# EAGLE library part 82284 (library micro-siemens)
MICROPROCESSOR/PERIPHERAL DEVICE
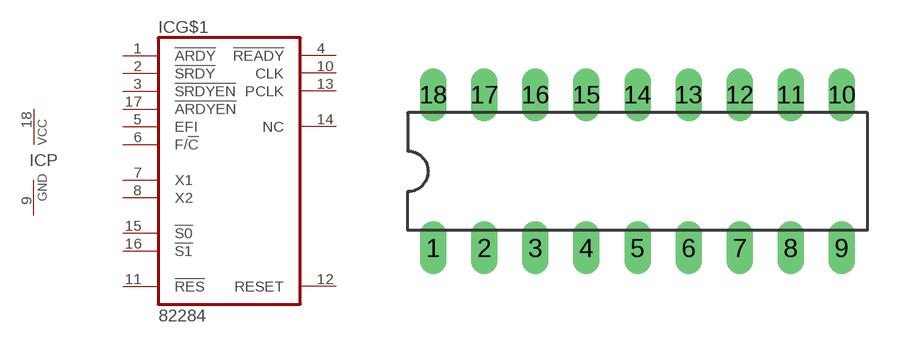
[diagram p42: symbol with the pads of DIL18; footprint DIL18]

Designator prefix IC; gates G$1=82284 P=VCCGND

## 82284 (OC_FARNELL: unknown; OC_NEWARK: unknown)  [DIL18]
1  G$1:!ARDY  in
2  G$1:!SRDY  in
3  G$1:!SRDYEN  in
4  G$1:!READY  out
5  G$1:EFI  in
6  G$1:F/!C  in
7  G$1:X1  in
8  G$1:X2  in
9  P:GND  pwr
10  G$1:CLK  out
11  G$1:!RES  in
12  G$1:RESET  out
13  G$1:PCLK  out
14  G$1:NC  nc
15  G$1:!S0  in
16  G$1:!S1  in
17  G$1:!ARDYEN  in
18  P:VCC  pwr

## Footprint DIL18 (pad centres in mm)
Dual In Line Package
drill 0.813 long: 1 -10.16,-3.81; 2 -7.62,-3.81; 3 -5.08,-3.81; 4 -2.54,-3.81; 5 0,-3.81; 6 2.54,-3.81; 7 5.08,-3.81; 8 7.62,-3.81; 9 10.16,-3.81; 10 10.16,3.81; 11 7.62,3.81; 12 5.08,3.81; 13 2.54,3.81; 14 0,3.81; 15 -2.54,3.81; 16 -5.08,3.81; 17 -7.62,3.81; 18 -10.16,3.81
